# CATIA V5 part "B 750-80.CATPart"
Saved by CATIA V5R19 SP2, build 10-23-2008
Part number: B 750-80
Bounding box of the stored display mesh (mm): x -22.494 to 22.494, y -22.494 to 22.494, z 0 to 245
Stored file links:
  C:\Users\Bora\Desktop\3D Katı model\B serisi\B 750\B 750-80.CATPart
  C:\Program Files\Dassault Systemes\B19\intel_a\reffiles\standard\MetricThickPitch.txt
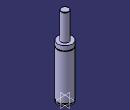
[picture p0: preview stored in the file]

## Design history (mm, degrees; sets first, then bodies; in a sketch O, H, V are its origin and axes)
Body1 (main body)
  Sketch1 on yz-plane, origin (0, 0, 0), H (0, 1, 0), V (0, 0, 1)
    point P3 (12, 244)
    point P5 (12, 244)
    point P7 (22.5, 149.5)
    point P8 (22.5, 147.5)
    point P12 (22.5, 147.5)
    point P13 (22.5, 149.5)
    line L1 (22.5, 0) -> (22.5, 4)
    line L2 (12, 244) -> (12, 163)
    arc A1 centre (11, 244) radius 1 from (12, 244) to (11, 245) ccw
    arc A2 centre (22.5, 148.5) radius 1 from (22.5, 149.5) to (22.5, 147.5) ccw
    line L3 (20, 7.5) -> (20, 4)
    line L4 (22.5, 7.5) -> (22.5, 147.5)
    line L5 (22.5, 149.5) -> (22.5, 163)
    line L6 (11, 245) -> (0, 245)
    point P15 (0, 245)
    line L7 (12, 163) -> (22.5, 163)
    line L8 (0, 0) -> (22.5, 0)
    line L9 (20, 4) -> (22.5, 4)
    line L10 (20, 7.5) -> (22.5, 7.5)
    coincidence: P15 V, P3 P5, P7 P13, P8 P12
    tangency: L6 A1
    horizontal: L7 H, L8 H, L9 H, L10 H
  Shaft1: profile Sketch1, axis Sketch1.V, angle 360
  Sketch2 on face of Shaft1 from Sketch1.L8, origin (0, 0, 0), H (1, 0, 0), V (0, -1, 0)
    point P1 (10, 0)
    distance P1 V = 10
  Hole1: placed by Sketch2, at (10, 0, 0) direction (0, 0, 1), diameter 6.647, depth 13, threaded "M8", thread diameter 8, thread depth 13, pitch 1.25
  CircPattern1: of Hole1, instances 2, angular step 180, axis from xy-plane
